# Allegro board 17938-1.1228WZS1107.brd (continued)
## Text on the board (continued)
User.44: This gerber is just for your reference to find the DP impedance traces in layer L2. | DP IMPEDANCE TABLE: L2 | * - Denotes that this Impedance | is NOT used | IMP(Ohm) | *65.0 | *68.0 | 70.0 | *72.0 | *75.0 | *80.0 | *83.0 | *85.0 | *88.0 | WIDTH(mils) | 6.0/5.0 | 5.5/5.0 | 5.0/4.0 | 5.0/5.0 | 4.5/5.0 | 3.5/4.0 | 3.5/4.5 | 3.5/5.5 | 3.5/7.5 | TYPE | DP | Ref. Plane | L1/L3
User.45: Slit | Note:Refer to DRILL layer for ELLIPSE drill direction | FIGURE | SIZE | 10.0 | 12.0 | 16.0 | 22.0 | 36.0 | 113.0 | 115.0 | 142.0 | 178.0 | 229.0 | 30.0 | 38.0 | 44.0 | 46.0 | 63.0 | 65.0 | 86.0 | 103.0 | 158.0 | 40.0x20.0 | 44.0x20.0 | 60.0x24.0 | 63.0x24.0 | 63.0x36.0 | 71.0x28.0 | 95.0x28.0 | 142.0x103.0 | DRILL CHART: TOP to BOTTOM | ALL UNITS ARE IN MILS | PLATED | NON-PLATED | QTY | 4088 | 26 | 533 | 19 | 1 | 5 | 4 | 3 | 2 | 7 | 8 | This gerber is just for your reference to find the DP impedance traces in layer L3. | This gerber is just for your reference to find the DP impedance traces in layer L4. | This gerber is just for your reference to find the DP impedance traces in layer L6. | This gerber is just for your reference to find the SE impedance traces in layer L2. | This gerber is just for your reference to find the SE impedance traces in layer L3. | This gerber is just for your reference to find the SE impedance traces in layer L4. | This gerber is just for your reference to find the SE impedance traces in layer L6. | DP IMPEDANCE TABLE: L3 | DP IMPEDANCE TABLE: L4 | DP IMPEDANCE TABLE: L6 | SE IMPEDANCE TABLE: L2 | SE IMPEDANCE TABLE: L3 | SE IMPEDANCE TABLE: L4 | SE IMPEDANCE TABLE: L6 | * - Denotes that this Impedance | is NOT used | Model | Bolt-L UMA MB | PCB_NO | 17938 | VER. | Layer | DRILL | L1 | L2SGND | L3 | TMASK | TPLACE | TSILK | TSMD | Designer | MOSSE | Date | 12/27/2018 | IMP(Ohm) | *33.0 | *65.0 | *35.0 | *68.0 | *37.5 | *70.0 | 70.0 | *40.0 | *72.0 | 40.0 | *42.0 | *75.0 | *43.0 | *80.0 | *45.0 | *83.0 | *48.0 | *85.0 | *50.0 | 50.0 | *52.0 | 85.0 | *55.0 | *88.0 | *60.0 | *90.0 | *95.0 | *100.0 | 100.0 | *110.0 | WIDTH(mils) | 6.5 | 11.0 | 6.0 | 5.0 | 4.5 | 8.5 | 4.0 | 8.0 | 3.9 | 7.5 | 3.5 | 7.0 | 5.5 | 11.5 | 10.5 | 9.0 | 10.0/5.0 | 9.0/5.0 | 8.5/5.0 | 7.5/4.5 | 7.0/4.0 | 6.0/4.5 | 5.0/4.0 | 6.0/6.0 | 5.5/5.0 | 5.0/4.5 | 5.0/5.0 | 5.0/6.0 | 4.0/4.0 | 4.0/5.0 | 3.5/4.0 | 4.0/7.0 | 3.5/5.0 | 5.0/11.0 | 4.0/12.0 | 3.5/8.0 | 8.0/5.0 | 6.5/3.5 | 8.0/6.0 | 7.5/5.0 | 6.0/3.5 | 6.5/4.0 | 5.5/3.5 | 7.0/6.0 | 4.5/3.5 | 4.5/4.0 | 5.0/5.5 | 4.5/4.5 | 4.0/4.5 | 5.0/8.0 | 4.0/6.5 | 4.0/9.0 | 3.5/7.0 | TYPE | SE | DP | Ref. Plane | L1/L3 | L5 | L2/L5 | L3/L5 | L2/L4 | BMASK | BPLACE | BSILK | BSMD | L4 | L5SGND | L6
